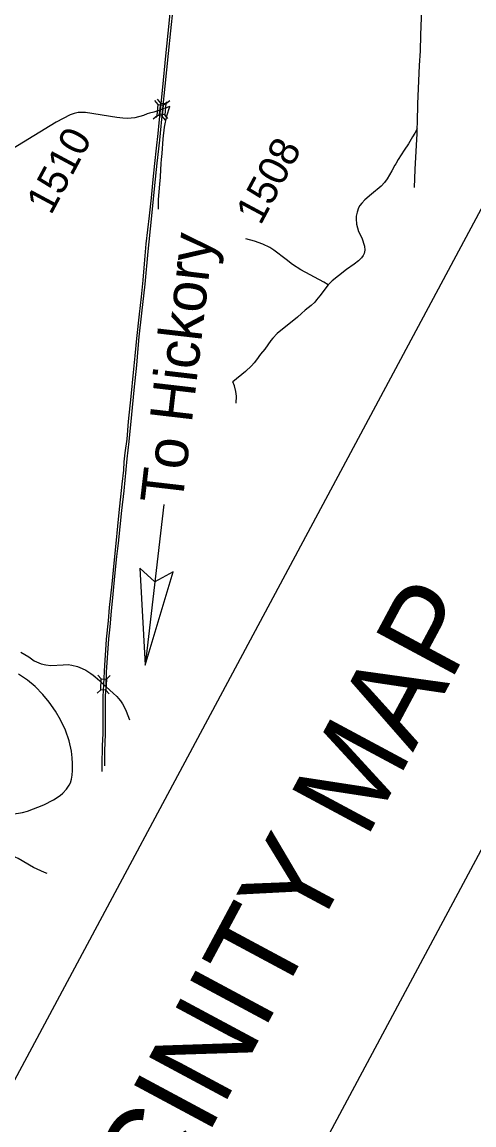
# Model space of a CAD drawing. Extents: x 1376167 to 1379209, y 761324 to 763997.
# Drawn here: x 1376708.2 to 1376772.1, y 762704.2 to 762860.1 of the extents above; entities that cross this region are included whole.
import ezdxf

# ---------------------------------------------------------------- set-up
doc = ezdxf.new("R2010")
doc.units = 0
for name, color, linetype in [('Default', 7, 'Continuous'), ('Old_Level_1', 7, 'Continuous'), ('Prop Terminator CELL', 7, 'Continuous'), ('Sheet Data Field CELL', 7, 'Continuous')]:
    doc.layers.add(name, color=color, linetype=linetype)

msp = doc.modelspace()

# ---------------------------------------------------------------- linework, layer by layer
at = {"layer": 'Default'}
for p, q in [((1376727.41, 762848.42), (1376726.96, 762848.97)), ((1376727.78, 762848.61), (1376727.33, 762849.17)), ((1376728.13, 762848.35), (1376728.68, 762848.81)), ((1376728.5, 762848.54), (1376729.05, 762848.99)), ((1376726.71, 762846.4), (1376727.26, 762846.85)), ((1376727.07, 762846.59), (1376727.62, 762847.05)), ((1376728.45, 762846.23), (1376727.99, 762846.78)), ((1376728.81, 762846.42), (1376728.35, 762846.97)), ((1376718.87, 762767.8), (1376719.36, 762767.27)), ((1376720.62, 762767.73), (1376720.09, 762767.24)), ((1376719.31, 762765.7), (1376718.78, 762765.22)), ((1376720.03, 762765.67), (1376720.51, 762765.15))]:
    msp.add_line(p, q, dxfattribs=at)
for points in [[(1376764.07, 762844.96), (1376764.11, 762845.94), (1376764.15, 762848.53), (1376764.38, 762853.94), (1376764.51, 762856.01), (1376764.57, 762858.24), (1376764.77, 762863.25), (1376764.9, 762864.43)], [(1376729.22, 762862.77), (1376728.95, 762859.86), (1376728.48, 762855.31), (1376728.02, 762850.85), (1376727.7, 762847.61)], [(1376728.07, 762847.79), (1376728.4, 762851), (1376728.89, 762855.62), (1376729.23, 762858.81), (1376729.53, 762861.94), (1376729.64, 762862.95)], [(1376727.45, 762833.64), (1376727.49, 762835), (1376727.68, 762837.18), (1376727.75, 762838.13), (1376727.74, 762838.25), (1376727.86, 762840.08), (1376727.89, 762840.63), (1376727.97, 762841.48), (1376728.15, 762843.55), (1376728.32, 762845.21), (1376728.66, 762846.8), (1376729.06, 762848.14)], [(1376729.06, 762848.14), (1376728.42, 762847.9), (1376728.07, 762847.79)], [(1376723.09, 762846.45), (1376722.41, 762846.5), (1376721.57, 762846.58), (1376717.14, 762847.28), (1376716.46, 762847.3), (1376716.1, 762847.28), (1376715.52, 762847.15), (1376714.97, 762846.97), (1376712.98, 762845.91), (1376705.19, 762841.17), (1376703.12, 762840.01)], [(1376727.7, 762847.61), (1376727.5, 762845.81), (1376727.36, 762844.32), (1376727.16, 762842.24), (1376726.92, 762840.09), (1376726.66, 762837.83), (1376726.41, 762835.23), (1376726.16, 762832.71), (1376725.66, 762828.72), (1376725.44, 762825.92), (1376725.25, 762823.6), (1376725.01, 762821.23), (1376724.74, 762818.79), (1376724.35, 762815.37), (1376724.13, 762812.91), (1376723.88, 762810.53), (1376723.55, 762807.17), (1376723.19, 762803.64), (1376722.97, 762801.13), (1376722.69, 762799.18), (1376722.58, 762797.93), (1376722.5, 762796.73), (1376722.27, 762794.77), (1376721.86, 762790.78), (1376721.68, 762788.85), (1376721.44, 762786.38), (1376721.13, 762783.6), (1376720.85, 762780.66), (1376720.49, 762777.35), (1376720.33, 762775.47), (1376720.05, 762772.89), (1376719.96, 762771.31), (1376719.83, 762769.21), (1376719.7, 762766.48)], [(1376720.05, 762766.12), (1376720.09, 762768.23), (1376720.45, 762772.92), (1376720.62, 762774.62), (1376720.82, 762776.83), (1376721.05, 762779.21), (1376721.3, 762781.77), (1376721.59, 762784.56), (1376721.81, 762786.43), (1376722.26, 762791.07), (1376722.62, 762793.81), (1376723.04, 762798.35), (1376723.3, 762800.79), (1376723.68, 762804.6), (1376724.03, 762808.06), (1376724.38, 762811.57), (1376724.58, 762813.93), (1376724.75, 762815.57), (1376725.12, 762818.95), (1376725.58, 762823.04), (1376726.03, 762827.63), (1376726.5, 762832.24), (1376726.95, 762836.98), (1376727.28, 762840.11), (1376727.64, 762843.37), (1376728.07, 762847.79)], [(1376727.7, 762847.61), (1376726.82, 762847.33), (1376726.2, 762847.21), (1376725.88, 762847.09), (1376725.36, 762846.87), (1376724.13, 762846.55), (1376723.09, 762846.45)], [(1376728.07, 762847.79), (1376727.7, 762847.61)], [(1376764.07, 762844.96), (1376763.73, 762844.36), (1376763.41, 762843.87), (1376762.82, 762842.86), (1376762.23, 762841.98), (1376761.39, 762840.66), (1376761.02, 762840.05), (1376760.91, 762839.86), (1376760.45, 762839.07), (1376759.8, 762837.94), (1376759.43, 762837.4), (1376758.95, 762836.88), (1376757.6, 762835.73), (1376756.67, 762834.97), (1376756.24, 762834.47), (1376755.97, 762834.15), (1376755.76, 762833.83), (1376755.55, 762833.23), (1376755.42, 762832.62), (1376755.42, 762832.25), (1376755.46, 762831.49), (1376755.78, 762830.48), (1376756.21, 762829.57), (1376756.63, 762828.41), (1376756.64, 762827.85), (1376756.55, 762827.36), (1376756.43, 762827.07), (1376756.17, 762826.74), (1376755.76, 762826.34), (1376755.14, 762825.85), (1376754.04, 762825.09), (1376752.93, 762824.23), (1376752.04, 762823.5), (1376751.48, 762822.96)], [(1376763.7, 762836.7), (1376763.79, 762839.22), (1376764.03, 762843.5), (1376764.05, 762844.24), (1376764.07, 762844.96)], [(1376751.48, 762822.96), (1376750.86, 762823.32), (1376747.58, 762825.07), (1376746.43, 762825.79), (1376745.51, 762826.54), (1376743.77, 762827.82), (1376743.24, 762828.2), (1376742.22, 762828.7), (1376741.06, 762829.1), (1376739.82, 762829.46)], [(1376751.48, 762822.96), (1376750.28, 762821.38), (1376749.83, 762820.8), (1376749.58, 762820.5), (1376749.04, 762820.03), (1376748.23, 762819.34), (1376747.7, 762818.9), (1376747.11, 762818.39), (1376744.27, 762816.05), (1376743.62, 762815.39), (1376743.38, 762815.06), (1376742.49, 762813.84), (1376741.9, 762813.13), (1376741.33, 762812.34), (1376741.01, 762811.9), (1376740.6, 762811.5), (1376739.79, 762810.7), (1376738, 762809.21)], [(1376738.47, 762806.21), (1376738.51, 762807.2), (1376738.41, 762807.87), (1376738.23, 762808.66), (1376738, 762809.21)], [(1376707.98, 762771.05), (1376709.11, 762770.36), (1376709.89, 762769.8), (1376710.89, 762769.4), (1376711.54, 762769.23), (1376712.26, 762769.17), (1376714, 762769.25), (1376714.68, 762769.28), (1376715.21, 762769.2), (1376715.99, 762769), (1376716.65, 762768.72), (1376717.2, 762768.48), (1376717.91, 762768.04), (1376718.24, 762767.78), (1376718.51, 762767.54), (1376719.17, 762766.97), (1376719.7, 762766.48)], [(1376706.79, 762748.14), (1376708.22, 762748.4), (1376708.93, 762748.57), (1376711.26, 762749.45), (1376712.6, 762750.15), (1376713.55, 762750.78), (1376713.93, 762751.11), (1376714.46, 762751.66), (1376714.85, 762752.22), (1376715, 762752.59), (1376715.16, 762753.1), (1376715.26, 762753.64), (1376715.31, 762754.29), (1376715.29, 762755.28), (1376715.26, 762756.09), (1376715.16, 762757.06), (1376714.81, 762758.5), (1376714.31, 762760), (1376713.62, 762761.46), (1376712.91, 762762.71), (1376712.01, 762763.96), (1376711.13, 762765.06), (1376710.04, 762766.16), (1376708.92, 762767.09), (1376707.67, 762767.93)], [(1376719.7, 762766.48), (1376719.59, 762764.77), (1376719.59, 762763.29), (1376719.6, 762760.58)], [(1376719.7, 762766.48), (1376719.86, 762766.31), (1376720.05, 762766.12)], [(1376719.95, 762760.39), (1376719.96, 762762.09), (1376719.98, 762764.84), (1376720.05, 762766.12)], [(1376720.05, 762766.12), (1376721.06, 762765.24), (1376721.58, 762764.79), (1376721.81, 762764.5), (1376722.09, 762764.17), (1376722.37, 762763.75), (1376722.6, 762763.31), (1376722.9, 762762.69), (1376723.37, 762761.46)], [(1376719.6, 762760.58), (1376719.59, 762759.51), (1376719.5, 762757.86), (1376719.46, 762755.04), (1376719.46, 762754.18)], [(1376719.87, 762754.95), (1376719.88, 762757.09), (1376719.95, 762759.46), (1376719.95, 762760.39)], [(1376711.72, 762739.74), (1376711.34, 762739.91), (1376709.81, 762740.62), (1376707.6, 762741.86), (1376705.04, 762743.03), (1376704.42, 762743.27), (1376703.76, 762743.48), (1376702.3, 762743.82), (1376695.84, 762744.77)]]:
    msp.add_lwpolyline(points, dxfattribs=at)
for points in [[(1376727.26, 762846.85), (1376727.41, 762848.42), (1376728.14, 762848.35), (1376727.99, 762846.78)], [(1376727.62, 762847.05), (1376727.78, 762848.61), (1376728.51, 762848.54), (1376728.35, 762846.97)], [(1376720.09, 762767.24), (1376720.03, 762765.67), (1376719.3, 762765.7), (1376719.36, 762767.27)]]:
    msp.add_lwpolyline(points, close=True, dxfattribs=at)
at = {"layer": 'Old_Level_1'}
for points in [[(1376622.61, 762553.05), (1376345.79, 762701.47), (1376550.88, 763083.99), (1376827.7, 762935.57)], [(1376345.79, 762701.47), (1376660.36, 762532.81), (1376865.45, 762915.33), (1376550.88, 763083.99)]]:
    msp.add_lwpolyline(points, close=True, dxfattribs=at)
at = {"layer": 'Prop Terminator CELL'}
msp.add_lwpolyline([(1376724.84, 762782.88), (1376725.59, 762769.2), (1376729.54, 762782.4), (1376726.96, 762780.97)], close=True, dxfattribs=at)
at = {"layer": 'Sheet Data Field CELL'}
msp.add_line((1376728.23, 762791.92), (1376725.59, 762769.2), dxfattribs=at)

# ---------------------------------------------------------------- texts
at = {"layer": 'Default'}
msp.add_text('To Hickory', height=6, rotation=83.3676, dxfattribs=at).set_placement((1376730.83, 762791.78))
at = {"layer": 'Old_Level_1'}
for s, height, p in [('1510', 4.185, (1376712.26, 762832.68)), ('1508', 4.185, (1376741.9, 762831.23)), ('VICINITY MAP', 12.5553, (1376721.13, 762677.89))]:
    msp.add_text(s, height=height, rotation=61.8015, dxfattribs=at).set_placement(p)

doc.saveas('drawing.dxf')
